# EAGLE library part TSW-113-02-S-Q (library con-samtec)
THROUGH-HOLE .025" SQ POST HEADER Source: Samtec TSW.pdf
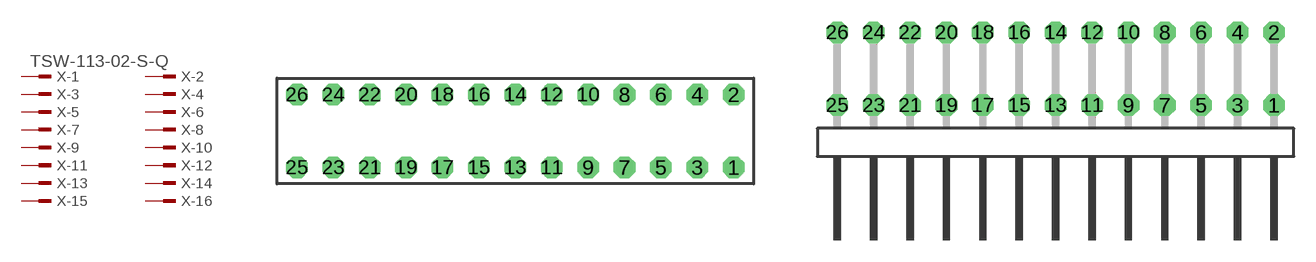
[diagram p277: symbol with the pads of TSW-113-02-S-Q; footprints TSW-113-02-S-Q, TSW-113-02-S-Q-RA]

Designator prefix X; gates -1=MPINV -2=MPIN -3=MPIN -4=MPIN -5=MPIN -6=MPIN -7=MPIN -8=MPIN -9=MPIN -10=MPIN -11=MPIN -12=MPIN -13=MPIN -14=MPIN -15=MPIN -16=MPIN -17=MPIN -18=MPIN -19=MPIN -20=MPIN -21=MPIN -22=MPIN -23=MPIN -24=MPIN -25=MPIN -26=MPIN

## TSW-113-02-S-Q (OC_FARNELL: unknown; OC_NEWARK: unknown)  [TSW-113-02-S-Q]
1  -1:1  pas
2  -2:1  pas
3  -3:1  pas
4  -4:1  pas
5  -5:1  pas
6  -6:1  pas
7  -7:1  pas
8  -8:1  pas
9  -9:1  pas
10  -10:1  pas
11  -11:1  pas
12  -12:1  pas
13  -13:1  pas
14  -14:1  pas
15  -15:1  pas
16  -16:1  pas
17  -17:1  pas
18  -18:1  pas
19  -19:1  pas
20  -20:1  pas
21  -21:1  pas
22  -22:1  pas
23  -23:1  pas
24  -24:1  pas
25  -25:1  pas
26  -26:1  pas

## TSW-113-02-S-Q-RA (OC_FARNELL: unknown; OC_NEWARK: unknown)  [TSW-113-02-S-Q-RA]
Pads as for TSW-113-02-S-Q

## Footprint TSW-113-02-S-Q (pad centres in mm)
THROUGH-HOLE .025" SQ POST HEADER Source: Samtec TSW.pdf
drill 1 pad 1.5 octagon: 1 15.24,-2.54; 2 15.24,2.54; 3 12.7,-2.54; 4 12.7,2.54; 5 10.16,-2.54; 6 10.16,2.54; 7 7.62,-2.54; 8 7.62,2.54; 9 5.08,-2.54; 10 5.08,2.54; 11 2.54,-2.54; 12 2.54,2.54; 13 0,-2.54; 14 0,2.54; 15 -2.54,-2.54; 16 -2.54,2.54; 17 -5.08,-2.54; 18 -5.08,2.54; 19 -7.62,-2.54; 20 -7.62,2.54; 21 -10.16,-2.54; 22 -10.16,2.54; 23 -12.7,-2.54; 24 -12.7,2.54; 25 -15.24,-2.54; 26 -15.24,2.54

## Footprint TSW-113-02-S-Q-RA (pad centres in mm)
THROUGH-HOLE .025" SQ POST HEADER Source: Samtec TSW.pdf
drill 1 pad 1.5 octagon: 1 15.24,1.524; 2 15.24,6.604; 3 12.7,1.524; 4 12.7,6.604; 5 10.16,1.524; 6 10.16,6.604; 7 7.62,1.524; 8 7.62,6.604; 9 5.08,1.524; 10 5.08,6.604; 11 2.54,1.524; 12 2.54,6.604; 13 0,1.524; 14 0,6.604; 15 -2.54,1.524; 16 -2.54,6.604; 17 -5.08,1.524; 18 -5.08,6.604; 19 -7.62,1.524; 20 -7.62,6.604; 21 -10.16,1.524; 22 -10.16,6.604; 23 -12.7,1.524; 24 -12.7,6.604; 25 -15.24,1.524; 26 -15.24,6.604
